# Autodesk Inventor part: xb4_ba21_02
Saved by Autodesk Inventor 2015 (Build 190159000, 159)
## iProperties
Created: 2018-04
Part Number: xb4_ba21_02
Checked By: TraceParts S.A.
Material: Generic
Catalog Web Link: www.traceparts.com
Document SubType Name: Modeling
Designer: TraceParts
Density: 1 g/cm^3
Appearance: Default
Company: TraceParts S.A.
Author: TraceParts
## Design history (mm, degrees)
feature "xb4_ba21_02.ipt"
body "Solid1"
